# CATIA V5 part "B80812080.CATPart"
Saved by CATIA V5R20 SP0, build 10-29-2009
Part number: B80812080
Revision: 6
Definition: design
Nomenclature: B80812080
Source: made
Description: NOT SPECIFIED
Bounding box of the stored display mesh (mm): x -8 to 8, y -8 to 8, z 0 to 80
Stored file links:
  C:\Users\Raffaele\Desktop\3D X SITO CF\BOLEX\4-PILLAR REF 808\B80812080.CATPart
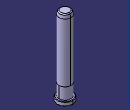
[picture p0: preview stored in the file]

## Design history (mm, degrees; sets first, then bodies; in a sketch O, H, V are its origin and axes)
Body1 "MANIFOLD_SOLID_BREP #450" (main body)
  Solid1: solid without history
